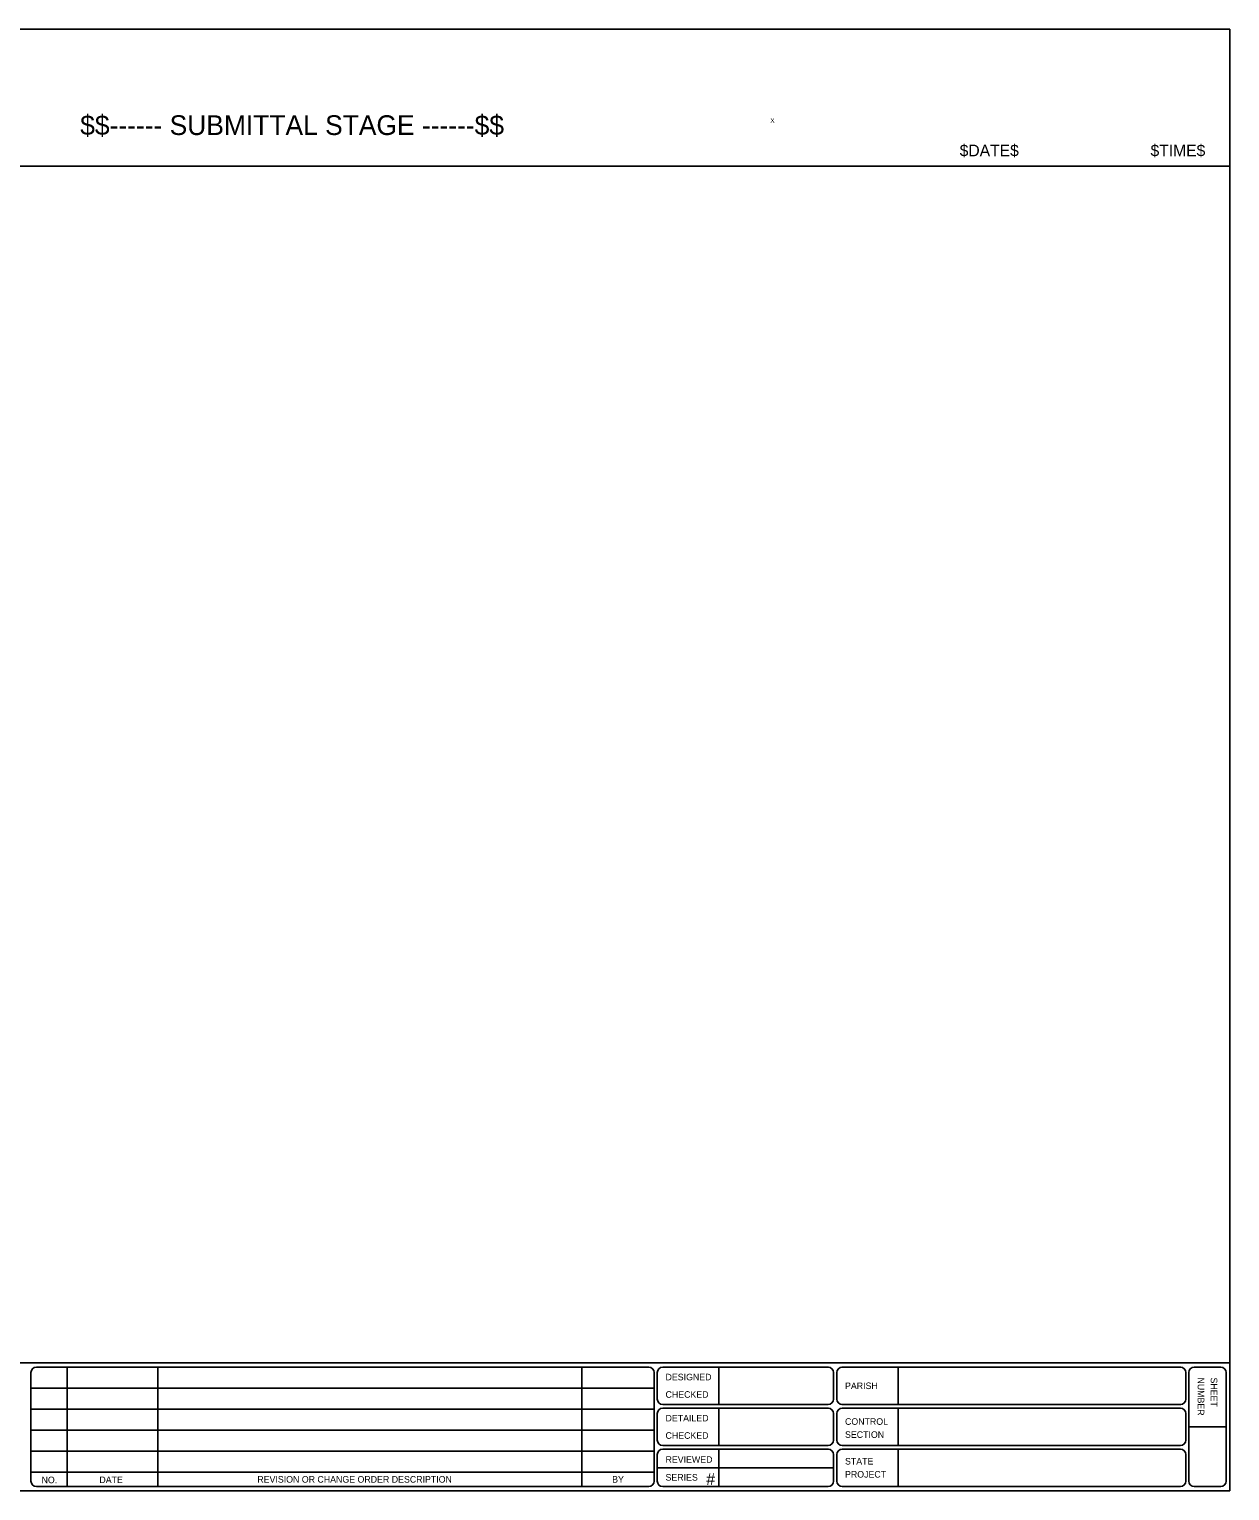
# Model space of a CAD drawing. Extents: x 0 to 21, y 0 to 16.
# Drawn here: x 7.86 to 21, y 0 to 16 of the extents above; entities that cross this region are included whole.
import ezdxf

# ---------------------------------------------------------------- set-up
doc = ezdxf.new("R2010")
doc.units = 0
for name, color, linetype in [('Annotation', 7, 'Continuous'), ('Construction Class', 7, 'Continuous'), ('Plot Border', 7, 'Continuous'), ('Sheet Border', 7, 'Continuous')]:
    doc.layers.add(name, color=color, linetype=linetype)

msp = doc.modelspace()

# ---------------------------------------------------------------- linework, layer by layer
at = {"layer": 'Construction Class'}
msp.add_line((16, 15), (16, 15), dxfattribs=at)
at = {"layer": 'Plot Border'}
msp.add_lwpolyline([(21, 0), (21, 16), (0, 16), (0, 0)], close=True, dxfattribs=at)
at = {"layer": 'Sheet Border'}
for p, q in [((21, 14.5), (0, 14.5)), ((21, 0), (21, 14.5)), ((21, 1.4), (0, 1.4)), ((7.882, 1.294), (7.882, 0.106)), ((14.643, 1.354), (7.941, 1.354)), ((8.278, 1.354), (8.278, 0.046)), ((9.269, 1.354), (9.269, 0.046)), ((13.909, 0.046), (13.909, 1.354)), ((14.701, 0.106), (14.701, 1.294)), ((14.736, 1.004), (14.736, 1.294)), ((16.608, 1.354), (14.796, 1.354)), ((15.41, 0.945), (15.41, 1.354)), ((16.663, 1.004), (16.663, 1.294)), ((16.699, 1.004), (16.699, 1.294)), ((20.464, 1.354), (16.754, 1.354)), ((17.373, 0.945), (17.373, 1.354)), ((20.52, 1.004), (20.52, 1.294)), ((20.551, 0.106), (20.551, 1.294)), ((20.901, 1.354), (20.611, 1.354)), ((20.96, 0.106), (20.96, 1.294)), ((14.701, 1.124), (7.882, 1.124)), ((14.701, 0.894), (7.882, 0.894)), ((14.736, 0.554), (14.736, 0.845)), ((16.603, 0.944), (14.796, 0.944)), ((16.608, 0.905), (14.796, 0.905)), ((15.41, 0.495), (15.41, 0.905)), ((16.663, 0.554), (16.663, 0.845)), ((16.699, 0.555), (16.699, 0.846)), ((20.465, 0.945), (16.754, 0.945)), ((20.46, 0.905), (16.759, 0.905)), ((17.373, 0.495), (17.373, 0.905)), ((20.52, 0.555), (20.52, 0.846)), ((14.701, 0.664), (7.882, 0.664)), ((20.96, 0.7), (20.551, 0.7)), ((16.603, 0.495), (14.796, 0.495)), ((20.461, 0.495), (16.758, 0.495)), ((14.701, 0.435), (7.882, 0.435)), ((14.736, 0.105), (14.736, 0.396)), ((16.608, 0.455), (14.796, 0.455)), ((15.41, 0.046), (15.41, 0.456)), ((16.663, 0.105), (16.663, 0.396)), ((16.699, 0.106), (16.699, 0.396)), ((20.46, 0.456), (16.759, 0.456)), ((17.373, 0.046), (17.373, 0.456)), ((20.52, 0.106), (20.52, 0.396)), ((14.701, 0.205), (7.882, 0.205)), ((14.736, 0.251), (16.663, 0.251)), ((21, 0), (0, 0)), ((14.643, 0.046), (7.941, 0.046)), ((16.603, 0.046), (14.796, 0.046)), ((20.46, 0.046), (16.759, 0.046)), ((20.901, 0.046), (20.611, 0.046))]:
    msp.add_line(p, q, dxfattribs=at)
for centre, start, end in [((7.941, 1.294), 90, 180), ((14.643, 1.294), 360, 90), ((14.795, 1.294), 90, 180), ((16.604, 1.294), 360, 90), ((16.759, 1.294), 90, 180), ((20.46, 1.294), 360, 90), ((20.61, 1.294), 90, 180), ((20.901, 1.294), 360, 90), ((14.795, 1.004), 180, 270), ((16.604, 1.004), 270, 360), ((16.759, 1.004), 180, 270), ((20.46, 1.004), 270, 360), ((14.795, 0.845), 90, 180), ((16.604, 0.845), 360, 90), ((16.759, 0.845), 90, 180), ((20.46, 0.845), 360, 90), ((14.795, 0.555), 180, 270), ((16.604, 0.555), 270, 360), ((16.759, 0.555), 180, 270), ((20.46, 0.555), 270, 360), ((14.795, 0.396), 90, 180), ((16.604, 0.396), 360, 90), ((16.759, 0.396), 90, 180), ((20.46, 0.396), 360, 90), ((7.941, 0.106), 180, 270), ((14.643, 0.106), 270, 360), ((14.795, 0.105), 180, 270), ((16.604, 0.105), 270, 360), ((16.759, 0.106), 180, 270), ((20.46, 0.106), 270, 360), ((20.61, 0.106), 180, 270), ((20.901, 0.106), 270, 360)]:
    msp.add_arc(centre, 0.0594, start, end, dxfattribs=at)

# ---------------------------------------------------------------- texts
at = {"layer": 'Annotation'}
msp.add_text('#', height=0.128, rotation=360, dxfattribs=at).set_placement((15.272, 0.063))
at = {"layer": 'Plot Border'}
for s, height, p in [('$$------ SUBMITTAL STAGE ------$$', 0.216, (8.421, 14.842)), ('$DATE$', 0.128, (18.045, 14.609)), ('$TIME$', 0.128, (20.133, 14.609))]:
    msp.add_text(s, height=height, rotation=360, dxfattribs=at).set_placement(p)
at = {"layer": 'Sheet Border'}
msp.add_text('X', height=0.05, dxfattribs=at).set_placement((15.973, 14.975))
for s, rotation, p in [('DESIGNED', 360, (14.826, 1.209)), ('PARISH', 360, (16.79, 1.113)), ('NUMBER', 270, (20.649, 1.24)), ('SHEET', 270, (20.792, 1.24)), ('CHECKED', 360, (14.826, 1.018)), ('DETAILED', 360, (14.826, 0.759)), ('CHECKED', 360, (14.826, 0.569)), ('CONTROL', 360, (16.79, 0.722)), ('SECTION', 360, (16.79, 0.579)), ('REVIEWED', 360, (14.826, 0.306)), ('STATE', 360, (16.79, 0.287)), ('REVISION OR CHANGE ORDER DESCRIPTION', 360, (10.359, 0.089)), ('BY', 360, (14.242, 0.089)), ('SERIES', 360, (14.826, 0.111)), ('PROJECT', 360, (16.79, 0.144)), ('NO.', 360, (7.998, 0.083)), ('DATE', 360, (8.631, 0.084))]:
    msp.add_text(s, height=0.072, rotation=rotation, dxfattribs=at).set_placement(p)

doc.saveas('drawing.dxf')
